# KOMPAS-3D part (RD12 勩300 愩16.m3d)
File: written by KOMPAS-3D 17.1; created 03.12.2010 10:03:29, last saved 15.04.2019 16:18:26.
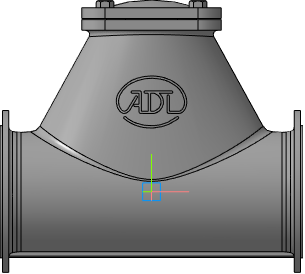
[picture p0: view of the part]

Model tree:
1. Плоскость XY
2. Плоскость ZX
3. Плоскость ZY
4. Ось X
5. Ось Y
6. Ось Z
7. Начало координат
8. Операция без истории:2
